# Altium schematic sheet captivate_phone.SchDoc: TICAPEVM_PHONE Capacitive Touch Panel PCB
size Letter; Date: Not shown in title block; ApprovedBy: Not shown in title block; CheckedBy: Not shown in title block; Author: Not shown in title block; CompanyName: Not shown in title block; Engineer: Not shown in title block; Organization: Not shown in title block; Address1: Not shown in title block; Address2: Not shown in title block; Address3: Not shown in title block; Address4: Not shown in title block; DocumentNumber: 1; Revision: Use project parameter SCH_Rev; SheetNumber: 1; SheetTotal: 1; PageSetup: Record=PageOptions¦CenterHorizontal=True¦CenterVertical=True¦PrintScale=0.94¦XCorrection=1.00¦YCorrection=1.00¦PrintKind=0¦BorderSize=5000000¦LeftOffset=0¦BottomOffset=0¦Orientation=2¦PaperLength=1000¦PaperWidth=1000¦Scale=100¦PaperSource=15¦PrintQuality=600¦MediaType=1¦DitherType=10¦PaperKind=Letter¦PrintScaleMode=1
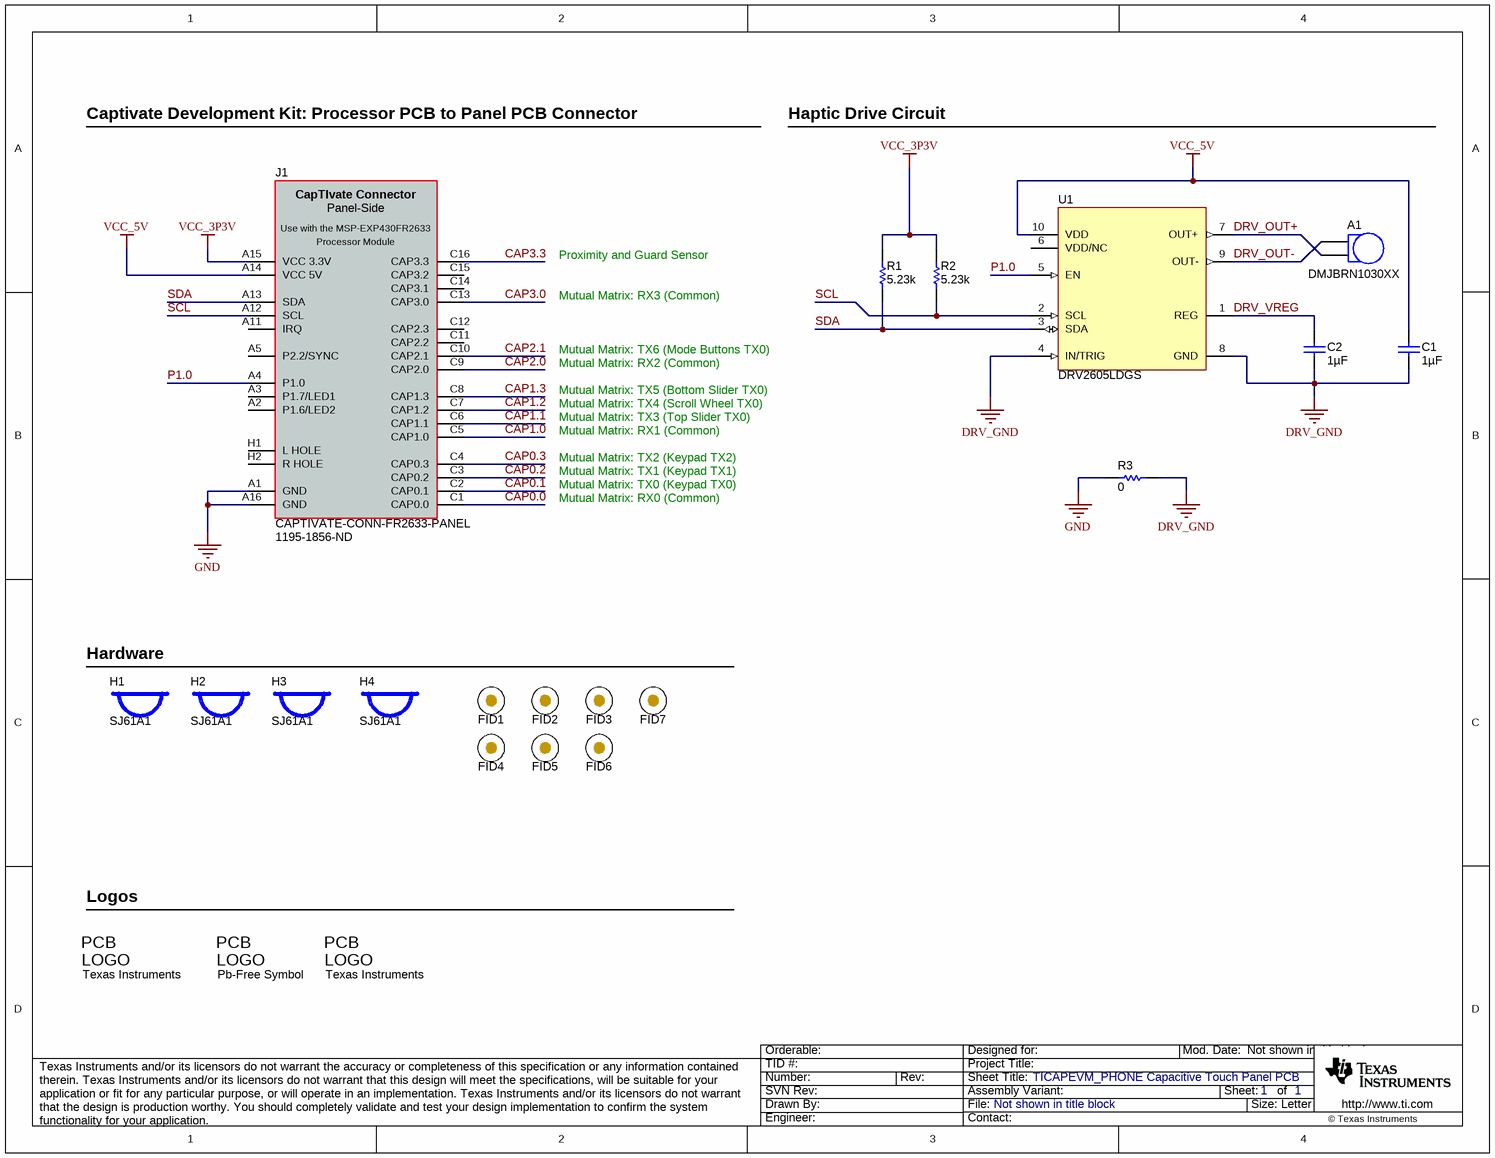
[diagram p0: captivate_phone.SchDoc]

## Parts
A1  DMJBRN1030XX  [SEMCO1030]
C1  ValueDisplayed: 1µF  [0603]  (hidden comment: C0603C105K8PACTU)
C2  ValueDisplayed: 1µF  [0603]  (hidden comment: C0603C105K8PACTU)
FID1  Fiducial  [Fiducial10-20]  (value not drawn)
FID2  Fiducial  [Fiducial10-20]  (value not drawn)
FID3  Fiducial  [Fiducial10-20]  (value not drawn)
FID4  Fiducial  [Fiducial10-20]  (value not drawn)
FID5  Fiducial  [Fiducial10-20]  (value not drawn)
FID6  Fiducial  [Fiducial10-20]  (value not drawn)
FID7  Fiducial  [Fiducial10-20]  (value not drawn)
H1  SJ61A1  [Bumpon_SJ61A1]
H2  SJ61A1  [Bumpon_SJ61A1]
H3  SJ61A1  [Bumpon_SJ61A1]
H4  SJ61A1  [Bumpon_SJ61A1]
J1  CAPTIVATE-CONN-FR2633-PANEL  Supplier Part Number 1: 1195-1856-ND  [CAPTIVATE-CONN-48]
Logo1  Pb-Free Symbol  [Pb-Free_Overlay_Medium]  (no BOM)
Logo2  Texas Instruments  [TI_Horizontal_Overlay_Medium]  (no BOM)
Logo3  Texas Instruments  [TI_Horizontal_Overlay_Medium]  (no BOM)
R1  ValueDisplayed: 5.23k  [0603]  (hidden comment: CRCW06035K23FKEA)
R2  ValueDisplayed: 5.23k  [0603]  (hidden comment: CRCW06035K23FKEA)
R3  ValueDisplayed: 0  [0603]  (hidden comment: CRCW06030000Z0EA)
U1  DRV2605LDGS  [DGS0010A_L]

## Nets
DRV_GND: C1.2 C2.2 R3.1 U1.4(IN/TRIG) U1.8(GND)
GND: J1.A1(GND) J1.A16(GND) R3.2
VCC_3P3V: J1.A15(VCC_3.3V) R1.2 R2.2
VCC_5V: C1.1 J1.A14(VCC_5V) U1.10(VDD)
CAP0.0: J1.C1(CAP0.0)
CAP0.1: J1.C2(CAP0.1)
CAP0.2: J1.C3(CAP0.2)
CAP0.3: J1.C4(CAP0.3)
CAP1.0: J1.C5(CAP1.0)
CAP1.1: J1.C6(CAP1.1)
CAP1.2: J1.C7(CAP1.2)
CAP1.3: J1.C8(CAP1.3)
CAP2.0: J1.C9(CAP2.0)
CAP2.1: J1.C10(CAP2.1)
CAP3.0: J1.C13(CAP3.0)
CAP3.3: J1.C16(CAP3.3)
DRV_OUT+: A1.2 U1.7(OUT+)
DRV_OUT-: A1.1 U1.9(OUT-)
DRV_VREG: C2.1 U1.1(REG)
P1.0: J1.A4(P1.0) U1.5(EN)
SCL: J1.A12(SCL) R2.1 U1.2(SCL)
SDA: J1.A13(SDA) R1.1 U1.3(SDA)

Not connected (* = marked no-connect by the designer): J1 A2(P1.6/LED2) A3(P1.7/LED1) A5(P2.2/SYNC) A11(IRQ) C11(CAP2.2) C12(CAP2.3) C14(CAP3.1) C15(CAP3.2) H1(L_HOLE) H2(R_HOLE); U1 6(VDD/NC)

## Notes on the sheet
- Captivate Development Kit: Processor PCB to Panel PCB Connector
- Haptic Drive Circuit
- Mutual Matrix: RX3 (Common)
- Proximity and Guard Sensor
- Mutual Matrix: RX2 (Common)
- Mutual Matrix: TX6 (Mode Buttons TX0)
- Mutual Matrix: RX1 (Common)
- Mutual Matrix: TX3 (Top Slider TX0)
- Mutual Matrix: TX4 (Scroll Wheel TX0)
- Mutual Matrix: TX5 (Bottom Slider TX0)
- Mutual Matrix: RX0 (Common)
- Mutual Matrix: TX0 (Keypad TX0)
- Mutual Matrix: TX1 (Keypad TX1)
- Mutual Matrix: TX2 (Keypad TX2)
- (near H1) Hardware
- (near Logo2) Logos

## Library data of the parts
A1 = DMJBRN1030XX: Linear Resonant Actuator; Manufacturer: Samsung Electro-Mechanics; SymbolCreator: a0273983; U/M: EA, IN, or GM
C1 C2 = C0603C105K8PACTU: CAP, CERM, 1 µF, 10 V, +/- 10%, X5R, 0603; Manufacturer: Kemet; Polarized: N; CompType: Capacitor; Value: 1uF; U/M: EA; Cap_F: 0.000001; Tolerance_%: 10; Value1: Unknown; Value2: 10V; TaMin_C: -55; TaMax_C: 85
FID1-FID7 = Fiducial: Fiducial mark.  There is nothing to buy or mount.; SymbolCreator: codlsc
H1-H4 = SJ61A1: Bumpon, Cylindrical, 0.312 X 0.200, Black; Manufacturer: 3M; SymbolCreator: a0412235
J1 = CAPTIVATE-CONN-MSP-EXP430FR2633-PANEL: CapTIvate Panel-Side Connector, 3x16, 100mil, TH, RA, M, MSP-EXP430FR2633; Manufacturer: Used in BOM report; SymbolCreator: a0273983; U/M: EA, IN, or GM
Logo1 = Pb-Free: SymbolCreator: a0412235
Logo2 = TI_Logo: Texas Instrument Corporate Signature; SymbolCreator: codlsc
Logo3 = TI_Logo: Texas Instrument Corporate Signature; SymbolCreator: a0412235
R1 R2 = CRCW06035K23FKEA: RES, 5.23 k, 1%, 0.1 W, 0603; Manufacturer: Vishay-Dale; CompType: Resistor; Value: 5.23k; Res_ohm: 5230; Value_Code: 5k23; Tolerance_%: 1; Power_W: 0.1; Value2: 0.1W; VDC_V: 75; TempCo: 100 ppm/C; EIA_Code: E96; U/M: EA
R3 = CRCW06030000Z0EA: RES, 0, 5%, 0.1 W, 0603; Manufacturer: Vishay-Dale; CompType: Resistor; Value: 0; Value_Code: 0000; Tolerance_%: 5; Power_W: 0.1; Value2: 0.1W; VDC_V: 75; TempCo: 200 ppm/C; EIA_Code: E24; U/M: EA
U1 = DRV2605LDGS: Haptic Driver for LRA and ERM With Built-In Library and Smart Loop Architecture, DGS0010A; Manufacturer: Texas Instruments; SymbolCreator: a0411947; CompType: IC; U/M: EA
